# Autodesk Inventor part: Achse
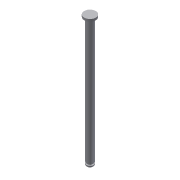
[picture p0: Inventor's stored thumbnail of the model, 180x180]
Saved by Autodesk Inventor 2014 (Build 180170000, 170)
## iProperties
Created: 2013-01
Part Number: Achse
Material: Aluminum 6061
Document SubType Name: Modeling
Designer: banachd
Density: 1 g/cm^3
Description: 3 mm DIA x 55.5 mm
Appearance: Aluminium - flach
Author: banachd
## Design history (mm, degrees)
sketch "Skizze1"
  geometry: C1 r 1.5 at (0, 0); 1 further point
  constraints: 1 centre point, 1 coincident
  dimensions: "d0" = 3 diameter of C1
extrude "Extrusion1" new body sketch "Skizze1" distance "d1" = 55.5; taper "d2" = 0 deg
sketch "Skizze2"
  geometry: C1 r 1.5 at (0, 0) reference; C2 r 2.5 at (0, 0)
  constraints: 1 centre point, 1 coincident
  dimensions: "d3" = 5 diameter of C2
extrude "Extrusion2" join sketch "Skizze2" distance "d4" = 1; taper "d5" = 0 deg
sketch "Skizze3"
  geometry: L1 (-1.5, 55.5)-(-2.5, 55.5) reference; L2 (-2.5, 55.5)-(-2.5, 56.5) reference; L3 (-2.5, 56.5)-(2.5, 56.5) reference; L4 (2.5, 56.5)-(2.5, 55.5) reference; L5 (2.5, 55.5)-(1.5, 55.5) reference; L6 (1.5, 55.5)-(1.5, 0) reference; L7 (1.5, 0)-(-1.5, 0) reference; L8 (-1.5, 0)-(-1.5, 55.5) reference; L9 (1.5, 1.5)-(1, 1.5); L10 (1, 1.5)-(1, 1); L11 (1, 1)-(1.5, 1); L12 (1.5, 1)-(1.5, 1.5); L13 (0, -11.4)-(0, 68.4) reference; 1 further point
  constraints: 8 end point, 2 parallel, 1 horizontal, 1 perpendicular, 1 point on line
  dimensions: "d6" = 54 distance from line of L5.end L9; "d7" = 0.5 distance between parallel lines of L11 L9; "d8" = 0.5 distance of L10.end L11.end
revolve "Revolution1" sketch "Skizze3" stored, may be unused: angle "d9" = 90 deg
chamfer "Chamfer1" distance "d11" = 0.5; stored, may be unused: second distance "d12" = 2, angle "d13" = 45 deg
body "Solid1"
node "Project Cut Edges1"
